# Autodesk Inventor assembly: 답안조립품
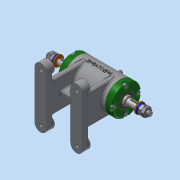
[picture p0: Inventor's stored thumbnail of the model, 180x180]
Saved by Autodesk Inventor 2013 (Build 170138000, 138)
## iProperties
Created: 2015-11
Part Number: 답안조립품
Document SubType Name: Assembly
Designer: Administrator
Author: Administrator
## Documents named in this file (16)
- C:\Users\Administrator\Desktop\451110V1049\답안조립품.iam
- C:\Users\Administrator\Desktop\451110V1049\본체.ipt
- C:\Users\Administrator\Desktop\451110V1049\V벨트풀리.ipt
- C:\Users\Administrator\Desktop\451110V1049\너트 M 8.ipt
- C:\Users\Administrator\Desktop\451110V1049\니플 M 6 x 0.75.ipt
- C:\Users\Administrator\Desktop\451110V1049\베어링 15 x 32 x 9.ipt
- C:\Users\Administrator\Desktop\451110V1049\볼트 M 6 x 8.ipt
- C:\Users\Administrator\Desktop\451110V1049\볼트 M4 x 12.ipt
- C:\Users\Administrator\Desktop\451110V1049\스퍼기어.ipt
- C:\Users\Administrator\Desktop\451110V1049\스프링와셔 8.ipt
- C:\Users\Administrator\Desktop\451110V1049\오일 실 15 25 7.ipt
- C:\Users\Administrator\Desktop\451110V1049\와셔 6x11.5.ipt
- C:\Users\Administrator\Desktop\451110V1049\와셔 8x17.ipt
- C:\Users\Administrator\Desktop\451110V1049\축.ipt
- C:\Users\Administrator\Desktop\451110V1049\커버.ipt
- C:\Users\Administrator\Desktop\451110V1049\키 3 x 3 x 12.ipt
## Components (11 placed, 3 different names)
1. V벨트풀리:1
2. KS B 2023 6002 - 15 x 32 x 9:1
3. KS B 2023 6002 - 15 x 32 x 9:2
4. ISO 4762 M4 x 12:1
5. ISO 4762 M4 x 12:3
6. ISO 4762 M4 x 12:4
7. ISO 4762 M4 x 12:5
8. ISO 4762 M4 x 12:2
9. ISO 4762 M4 x 12:6
10. ISO 4762 M4 x 12:7
11. ISO 4762 M4 x 12:8
